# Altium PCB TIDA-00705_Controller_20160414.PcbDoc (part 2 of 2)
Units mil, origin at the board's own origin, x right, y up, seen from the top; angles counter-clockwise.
Board outline 1000 x 1000 mil, 4 copper layers (Top Layer, L2-GND-PLANE, L3-GND-PLANE, Bottom Layer), stack 0 mil thick; 95 components, 61 nets, 268 pads, 111 vias.
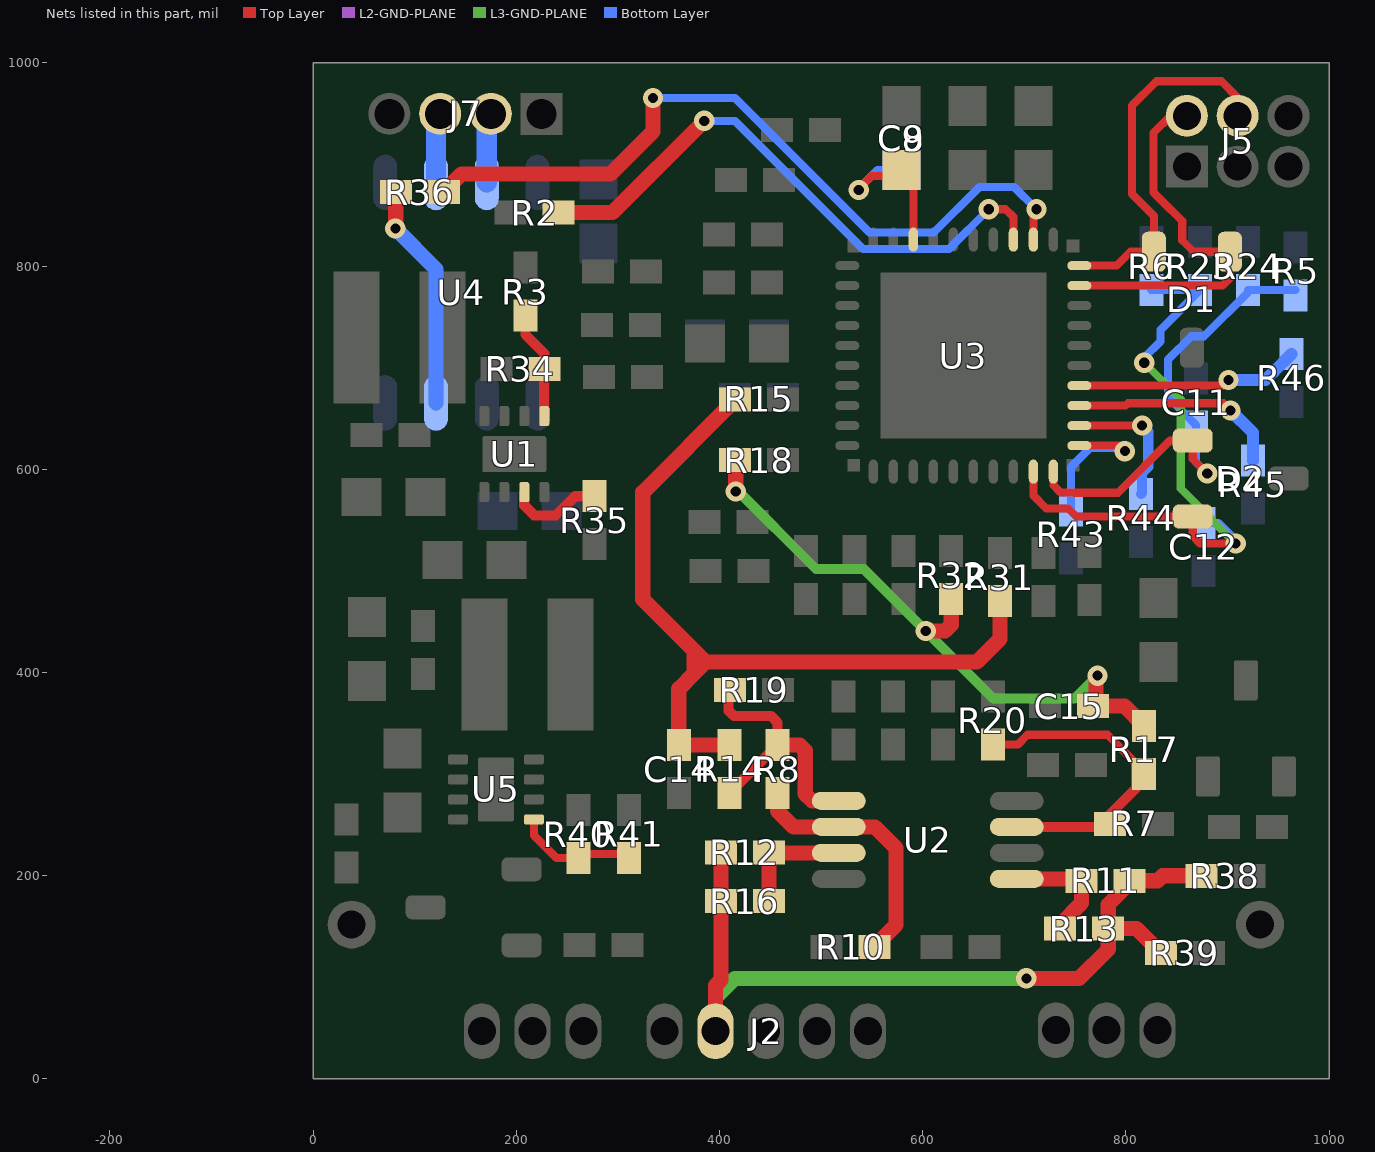
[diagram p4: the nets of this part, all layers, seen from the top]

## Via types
v1: diameter 20, hole 10, Top Layer to Bottom Layer, tented both sides, 76 vias
v2: diameter 20, hole 10, Top Layer to Bottom Layer, 26 vias
v3: diameter 19.68, hole 7.87, Top Layer to Bottom Layer, tented both sides, 5 vias
v4: diameter 19.68, hole 7.87, Top Layer to Bottom Layer, 4 vias

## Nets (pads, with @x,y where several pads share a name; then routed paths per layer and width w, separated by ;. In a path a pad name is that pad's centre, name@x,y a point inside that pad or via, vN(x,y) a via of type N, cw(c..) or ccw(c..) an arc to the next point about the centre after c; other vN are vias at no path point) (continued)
NetR7_2: R7.2 R17.1 R20.2 U2.7 | length 308.2
  Top Layer w8: R20.2@675,329.38 693.81,329.38 703.22,338.78 781.78,338.78 R17.1@810,310.57
  Top Layer w10: U2.7@692.6,248.13 772.13,248.13 810,286 R17.1@810,310.57
NetR8_1: R8.1 R10.2 U2.2 | length 255.6
  Top Layer w15: R8.1@457,281.38 457,263.96 473,247.96 552.87,248.13 573.62,227.38 573.62,151.62 R10.2@552,130
NetR8_2: R8.2 R14.1 R19.2 U2.1 | length 268.4
  Top Layer w10: R14.1@410,281.38 410,281.62 R8.2@457,328.62 457,351 450.63,357.37 414.13,357.37 409,362.5 409,373.62 R19.2@416.38,381
  Top Layer w15: R8.2@460,328.62 478.88,328.62 484.31,323.19 484.31,280.69 491.28,273.72 U2.1@517.4,273.72
NetR11_2: R11.2 R13.2 U2.5 | length 119.5
  Top Layer w15: U2.5@692.6,196.94 756.32,196.94 756.38,197 756.38,173.24 735.38,152.24 R13.2@735.38,150
NetR12_2: R12.2 R16.2 U2.3 | length 117.8
  Top Layer w15: R16.2@448.62,175 R12.2@448.62,223 ; R12.2@448.62,225 451.09,222.54 U2.3@517.4,222.54
NetR35_1: R35.1 U1.3 | length 94.1
  Top Layer w10: U1.3@207.84,577.6 207.84,564.59 217.68,554.76 239.13,554.76 258,573.62 R35.1@277,573.62
NetR36_1: R36.1 U4.3 | length 225.2
  Top Layer w15: v2(81,837) 81.38,837.38 R36.1@81.38,873
  L2-GND-PLANE w15: v2(81,837) v2@81,838
  Bottom Layer w15: v2(81,837) 121,797 U4.3@121,665.5
NetR43_1: R43.1 U3.11 | length 152.7
  Top Layer w8: U3.11@754.17,623.42 795.58,623.42 799,620 v1(799,618)
  Bottom Layer w8: R43.1@746,559.77 746,602.25 764.75,621 796,621 v1(799,618)
NetR44_1: R44.1 U3.12 | length 136.6
  Top Layer w8: U3.12@754.17,643.1 v1(816,643.1) v1@817.9,643.1
  Bottom Layer w10: R44.1@815,575.62 816,576.62 816,596.47 822,602.47 822,637.1 v1(816,643.1)
NetR45_1: R45.1 U3.13 | length 211.2
  Top Layer w8: U3.13@754.17,662.79 799.69,662.79 802,665.1 895.9,665.1 v1(903,658)
  Bottom Layer w12: v1(903,658) 925,636 R45.1@925,608.62
NetR46_1: R46.1 U3.14 | length 221.7
  Top Layer w8: U3.14@754.17,682.47 895.47,682.47 v1(901,688)
  Bottom Layer w12: v1(901,688) 937.26,688 945.39,696.13 945.5,696.13 R46.1@963,713.62
PHASE1_CBC: C14.1 R14.2 R15.1 R31.2 | length 824.9
  Top Layer w15: R14.2@410,328.62 C14.1@360,328.62 360,384 375,399 ; R15.1@415.38,668.32 324.5,577.44 324.5,472.12 375,421.62 ; R31.2@676,472.38 676,433 653.31,410.31 386.31,410.31 ; 375,399 375,421.62 ; 375,399 386.31,410.31 ; 375,421.62 386.31,410.31
PHASE2_CBC: C15.1 R17.2 R18.1 R32.2 | length 620.5
  Top Layer w15: R18.1@415.38,611 416,610.38 v1@416,581 ; v1(603,441) 622,441 628,447 R32.2@628,472.38 ; v1(772,397) 771.24,397 770.62,396.38 770.62,367 798.62,367 R17.2@818,347.62
  L3-GND-PLANE w10: v1@416,581 495,502 542,502 v1(603,441) 669.62,374.38 749.38,374.38 v1(772,397)
  other v1: 416,578.19
PMBUS-ALERT: D1.1 J5.2 U3.19 | length 386.1
  Top Layer w8: U3.19@754.28,781 U3.19@754.17,780.9 781.79,780.9 781.89,781 895,781 902.4,788.4 D1.1@902.4,814.24 866.76,814.24 855.5,825.5 855.5,844.5 834.67,865.33 834.36,865.33 827.33,872.36 827.33,931.33 844,948 J5.2@860,948
PMBUS-CLK: C12.1 D2.2 R6.1 R23.1 U3.9 | length 653.1
  Top Layer w8: U3.9@708.9,597.83 708.9,574.1 721.63,561.37 742.41,561.37 742.78,561 743.78,561 751.18,553.6 D2.2@865.76,553.6 865.76,534.24 873,527 v2(908,527)
  L3-GND-PLANE w8: v2(818.04,704.98) 854,669.02 854,581 v2(908,527)
  Bottom Layer w8: v2(818.04,704.98) 818.04,709.93 834,725.89 834,737.38 R23.1@873,776.38 R6.1@825,776.38 ; C12.1@876.38,547.24 891.19,547.24 908,530.43 v2(908,527)
PMBUS-CTRL: D1.2 J5.4 U3.20 | length 370.4
  Top Layer w8: U3.20@754.17,800.58 791,800.58 804.66,814.24 D1.2@827.6,814.24 827.6,849.33 806,870.93 806,958 830,982 894,982 910,966 J5.4@910,948
PMBUS-DATA: C11.1 D2.1 R5.1 R24.1 U3.10 | length 496.4
  Top Layer w8: U3.10@728.58,597.83 728.58,584.42 735.63,577.37 749.04,577.37 749.41,577 792.11,577 843.51,628.4 D2.1@865.76,628.4 865.76,610.24 v1(880,596)
  Bottom Layer w8: v1(880,596) 869,607 C11.1@869,642.38 869,643.84 841.49,671.35 841.49,708.02 864.47,731 877,731 920,774 R24.1@920,776.38 R5.1@967,776.38
SCI_RX: R2.2 U3.23 | length 578.6
  Top Layer w8: v1(665,856) 681.46,856 689.21,848.24 U3.23@689.21,826.17
  Top Layer w15: R2.2@241.62,852.75 294.75,852.75 v1(385,943)
  Bottom Layer w8: v1(385,943) 415.11,943 541.11,817 626,817 v1(665,856)
SCI_RX_ISO: J7.2 U4.7 | length 69.2
  Bottom Layer w20: U4.7@171,882.5 171,946 J7.2@175,950
SCI_TX: R36.2 U3.22 | length 754.8
  Top Layer w8: U3.22@708.9,826.17 708.9,852.9 v1(712,856)
  Top Layer w15: R36.2@128.62,873 146.24,890.62 292.62,890.62 334.5,932.5 v1(334.5,965.5)
  Bottom Layer w8: v1(334.5,965.5) 415.24,965.5 547.74,833 610.89,833 655.89,878 690,878 v1(712,856)
SCI_TX_ISO: J7.3 U4.6 | length 69.2
  Bottom Layer w20: U4.6@121,882.5 121,946 J7.3@125,950
V8.2FB: R40.1 R41.2 U5.5 | length 120.3
  Top Layer w8: U5.5@217.4,255.47 217.4,239.72 239.75,217.38 R40.1@261,217.38 ; R40.1@261,221.38 307,221.38 R41.2@311,217.38
VFB: R3.2 R34.1 U1.5 | length 106.7
  Top Layer w10: R3.2@209,751.38 209,732.63 227.62,714.01 R34.1@227.62,699 227.53,698.91 U1.5@227.53,652.4
VREF: C8.2 C9.1 U3.28 | length 174.5
  Top Layer w8: v1(537,875) 537,876 550,889 573.5,889 C8.2@579,894.5 590.79,882.72 U3.28@590.79,826.17
  Bottom Layer w8: v1(537,875) 537,876 555.5,894.5 C9.1@579,894.5
VREF_OA: J2.4 R11.1 R12.1 R13.1 R16.1 R38.1 R39.2 | length 828.2
  Top Layer w15: J2.4@396,47 396,92 401.38,97.38 R16.1@401.38,175 R12.1@401.38,223 ; v1(702,99) 754,99 782.62,127.62 R13.1@782.62,148 ; R39.2@834.38,124 810.38,148 R13.1@782.62,148 ; R38.1@874.38,200 836,200 831,195 R11.1@803.62,195 803.62,192.76 782.62,171.76 R13.1@782.62,148
  L3-GND-PLANE w15: J2.4@396,47 396,80 415,99 v1(702,99)
pads on no net: D4.3 U1.4 U1.8 U3.2 U3.8 U3.15 U3.21 U3.24 U3.25 U3.42 U5.4 U5.8

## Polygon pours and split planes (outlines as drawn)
GND on Bottom Layer "Top Layer-No Net" (solid, remove dead copper, pour order 14): 37.2,987.2 10,960 10,611 10,37 10,22 22,10 977,10 978,10 990,22 990,978 978,990
BUS+ on Top Layer "Top Layer-No Net" (solid, remove dead copper, pour order 21): 180,586 180,579 180,557 169,546 168,545 168,533 168,492 170,490 171,489 180,489 283,489 287,493 290,496 290,510 290,542 288,544 280,544 205,544 198,551 197,552 197,564 197,587 194,590 187,590 182.46,590 180,587.54
NetL1_1 on Top Layer "Top Layer-No Net" (solid, remove dead copper, pour order 19): 100,801 100,764 100,663 105,658 109,654 150,654 163,667 177,667 178,667 180,665 180,660 180,642 181,641 186,641 193,641 194,642 195,643 195,647 195,679 193,681 192,682 176,682 163,682 158,687 158,700 158,799 153,804 121,804 103,804
3.3V on Top Layer "Top Layer-No Net" (solid, remove dead copper, pour order 17): 16,785 16,735 16,530 27,519 34,512 57,512 72,512 75,515 77,517 77,603 77,806 68,815 67,816 49.54,816 28,816 16,804
GND on Top Layer "Top Layer-No Net" (solid, remove dead copper, pour order 13): 37.2,987.2 10,960 10,611 10,37 10,22 22,10 977,10 978,10 990,22 990,978 978,990
BUS+ on Top Layer "Top Layer-No Net" (solid, remove dead copper, pour order 8): 30.54,293.04 17.5,280 17.5,257 17.5,242.5 22,238 23,237 37,237 106.98,237 111,241.02 113,243.02 113,255 113,274 115,276 124,285 140,285 151,285 153,287 154,288 154,294 154,302 152,304 138,304 41.5,304
8.2V on Top Layer "Top Layer-No Net" (solid, remove dead copper, pour order 10): 20,496 20,450 20,444 25,439 29,435 64,435 86,435 91,430 94,427 112,427 131,427 134,424 139,419 139,369 139,346 144,341 152,341 192,341 198,347 198,359 198,470 194,474 192,476 123,476 93.18,476 80.2,488.98 65.18,504 28,504
NetL2_1 on Top Layer "Top Layer-No Net" (solid, remove dead copper, pour order 12): 209,302 227,302 229,304 235,310 235,322 229,328 229,346 229,472 233,476 265,476 283,476 287,472 290,469 290,447 290,302.5 280.5,293 261,293 239,293 233,287 213,287 209,287 205,291 205,297 205,299 208,302
GND on L3-GND-PLANE "Top Layer-No Net" (solid, remove dead copper, pour order 11): 36.2,987.2 9,960 9,611 9,37 9,22 21,10 976,10 977,10 989,22 989,978 977,990
GND on L2-GND-PLANE "Top Layer-No Net" (solid, remove dead copper, pour order 9): 37.2,987.2 10,960 10,611 10,37 10,22 22,10 977,10 978,10 990,22 990,978 978,990

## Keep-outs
Keep-Out Layer:
  lines w6: 10,10 990,10 990,990 10,990 10,10
  text ".Layer_Name" at 577,-858.49 h60

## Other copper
Top Layer:
  pour cut-out: 16,913 12,909 10,909 10,913 12.16,915.16
  pour cut-out: 10,917.33 14.33,913 218,913 290,913 308,931 308,981 299,990 24,990 10,976
  text ".Layer_Name" at 577,-858.49 h60
L2-GND-PLANE:
  pour cut-out: 10,917.33 14.33,913 218,913 290,913 308,931 308,981 299,990 24,990 10,976
  pour cut-out: 16,913 12,909 10,909 10,913 12.16,915.16
  text ".Layer_Name" at 612,-866 h60
L3-GND-PLANE:
  pour cut-out: 16,913 12,909 10,909 10,913 12.16,915.16
  pour cut-out: 10,917.33 14.33,913 218,913 290,913 308,931 308,981 299,990 24,990 10,976
  text ".Layer_Name" at 640,-860 h60
Bottom Layer:
  pour cut-out: 10,917.33 14.33,913 218,913 290,913 308,931 308,981 299,990 24,990 10,976
  pour cut-out: 16,913 12,909 10,909 10,913 12.16,915.16
  text ".Layer_Name" at 577,-858.49 h60

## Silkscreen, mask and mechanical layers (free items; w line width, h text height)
Top Overlay:
  circle w10: c717.72,111 r7.28
  circle w10: c109,82 r7.28
  lines w6: 45,668 45,677 ; 313,656 350,656 375,681 ; 315,881 323,873 352,873 373.5,851.5 375,851.5 ; 347,832 350,832 363,819 363,804 363,782 368,777 372,777 ; 477,558 788,558 799,547 799,514 ; 539,854 604.78,854 616.8,866.02 ; 550,436 787,436 795,444 ; 664,180 684,160 702,160 ; 681,58 681,97 ; 718,184 725,184 ; 801,536 810,536 ; 10,581 20,571 147.01,571 176.01,542 243,542 260,559 260,605 246,619 223,642 191.98,642 166.98,667 19,667 10,658 10,581
  text "A" at 51,679 h30 r90
  text "A" at 810,527 h30
  text ".Layer_Name" at 577,-858.49 h60
Bottom Overlay:
  lines w6: 844,587.99 844,596.5 854,606.5
  text "TIDA-00705" at 334,431 h35
  text "Rev E1" at 278,381 h40
  text ".Layer_Name" at 577,-858.49 h60
Top Paste:
  text ".Layer_Name" at 577,-858.49 h60
Bottom Paste:
  text ".Layer_Name" at 577,-858.49 h60
Top Solder:
  text ".Layer_Name" at 577,-858.49 h60
  text ".Layer_Name" at 577,-858.49 h60
Bottom Solder:
  text ".Layer_Name" at 577,-858.49 h60
Drill Guide:
  text ".Layer_Name" at 577,-858.49 h60
M1 Board Outline:
  lines w5.98: 0,0 0,1000 1000,1000
  lines w6: 0,0 0,1000 1000,1000 ; 0,0 1000,0 ; 0,0 1000,0 ; 1000,0 1000,1000 ; 1000,0 1000,1000
  text ".Layer_Name" at 567,-866 h60
M2 Board Dimensions:
  rectangle: -0.5,-285.5 124.5,-160.5
  rectangle: 124.5,-410.5 499.5,-285.5
  lines w7: -0.5,-285.5 999.5,-285.5 ; 124.5,-410.5 124.5,-160.5 ; 249.5,-410.5 249.5,-160.5 ; 499.5,-410.5 499.5,-160.5 ; 749.5,-410.5 749.5,-160.5 ; -0.5,-410.5 999.5,-410.5 999.5,-160.5 -0.5,-160.5 -0.5,-410.5
  lines w10: -0.5,-475.5 -0.5,-455.5 ; 59.5,-485.5 -0.5,-465.5 ; 59.5,-445.5 -0.5,-465.5 ; 223.58,-465.5 -0.5,-465.5 ; 775.42,-465.5 999.5,-465.5 ; 939.5,-485.5 999.5,-465.5 ; 939.5,-445.5 999.5,-465.5 ; 999.5,-475.5 999.5,-455.5
  text "1000 (mil)" at 233.58,-501.49 h60
M3 3D STEP Top:
  text ".Layer_Name" at 577,-858.49 h60
M4 3D STEP Bottom:
  text ".Layer_Name" at 577,-858.49 h60
M5 Assembly Top:
  circle w15: c551,624 r6
  circle w10: c166,47 r9.22
  circle w10: c555,47 r9.22
  circle w10: c740,48 r9.22
  circle w10: c226,929 r9.22
  circle w10: c933,812 r9.22
  circle w10: c865,654 r9.22
  circle w6: c856,302 r9.22
  lines w10: -292,-930.17 6308,-930.17 ; -292,-726.83 6310,-726.83 ; -292,-523.5 -292,-1133.5 3713,-1133.5 6310,-1133.5 6310,-523.5 -291.5,-523.5 -291.5,-1133.5 1284,-1133.5 ; 2173,-1133.5 2173,-523.5 ; 3735,-726 3735,-522.67 ; 4280,-726.83 4280,-523.5 ; 4902,-1140 4902,-937.17
  text "COMPONENTS MARKED 'DNP' SHOULD NOT BE POPULATED." at 1153.5,-318.5 h30
  text "ASSEMBLY VARIANT:" at 1153,-434 h30
  text ".VariantName" at 2189,-434 h30
  text "PCB VIEWED FROM TOP SIDE" at -228.5,-655.67 h30
  text "BOARD #:" at 2248,-655.67 h30
  text "ISE-PLC-AIM-300" at 2793.5,-655.67 h30
  text "SVN REV:" at 4476,-655.67 h30
  text ".VersionControl_RevNumber" at 4982,-655.67 h30
  text "REV: E1" at 3805,-660 h30
  text "IGNORE ->" at -228.5,-858.49 h30
  text ".LAYER_Name" at 586,-863 h60
  text "PLOT NAME =" at -228.5,-1064.34 h30
  text ".plot_File_Name" at 577,-1064.34 h30
  text "GENERATED    :" at 2250,-1064.34 h30
  text ".Print_Date" at 3119.5,-1064.34 h30
  text ".Print_Time" at 3848.5,-1064.34 h30
  text "TEXAS INSTRUMENTS" at 5113,-1064.34 h30
M6 Assembly Bottom:
  lines w10: -292.5,-727.33 6309.5,-727.33 ; -290.5,-930.67 6309.5,-930.67 ; 1115.5,-1140.5 1115.5,-937.67 ; 1737.5,-727.33 1737.5,-524 ; 2236,-723 2236,-519.67 ; 3844.5,-1134 3844.5,-524 ; 4733.5,-1134 6309,-1134 6309,-524 -292.5,-524 -292.5,-1134 2304.5,-1134 6309.5,-1134 6309.5,-524
  text "COMPONENTS MARKED 'DNP' SHOULD NOT BE POPULATED." at 6102,-318 h60
  text ".VariantName" at 5058,-434 h60
  text "ASSEMBLY VARIANT:" at 6097,-434 h60
  text "REV: E1" at 2173,-655 h60
  text ".VersionControl_RevNumber" at 1035.5,-656.17 h60
  text "SVN REV:" at 1541.5,-656.17 h60
  text "ISE-PLC-AIM-300" at 3224,-656.17 h60
  text "BOARD #:" at 3769.5,-656.17 h60
  text "PCB VIEWED FROM BOTTOM SIDE" at 6246,-656.17 h60
  text ".layer_Name" at 5851,-844 h60
  text "IGNORE ->" at 2547.85,-858.49 h60
  text "TEXAS INSTRUMENTS" at 904.5,-1064.84 h60
  text ".Print_Time" at 2169,-1064.84 h60
  text ".Print_Date" at 2898,-1064.84 h60
  text "GENERATED    :" at 3767.5,-1064.84 h60
  text ".plot_File_Name" at 5440.5,-1064.84 h60
  text "PLOT NAME =" at 6246,-1064.84 h60
M7 LPKF Text Top:
  lines w6: 16.94,472 16.94,180.66 17.61,180 954.46,180 956,181.54 956,470.76 954.82,471.95 17,471.95 18.06,470.88
M9 Title Sheet:
  drawing of 56 lines, arcs and shapes, not listed
  text "1" at 320.58,8044.9 h70
  text "2" at 3262.11,8044.9 h70
  text "3" at 5702.71,8044.9 h70
  text "4" at 8212.65,8044.9 h70
  text "5" at 10776.84,8044.9 h70
  text "6" at 13282.14,8044.9 h70
  text "A" at -399.13,6895.37 h70
  text "A" at 14398.02,6895.37 h70
  text "B" at -399.13,4636.49 h70
  text "B" at 14398.02,4636.49 h70
  text "C" at -399.13,2204.83 h70
  text "C" at 14398.02,2204.83 h70
  text "PROJECT TITLE:" at 11348.77,257.82 h45
  text ".PRJ_Title" at 11440.27,127.32 h70
  text "DESIGNED FOR:" at 11335.61,-31.74 h45
  text ".PRJ_Customer" at 11385.61,-171.74 h70
  text "D" at -399.13,-301.67 h70
  text "D" at 14398.02,-301.67 h70
  text "FILE NAME:" at 11347.5,-340.46 h45
  text ".PCB_File_Name_No_Path" at 11397.5,-460.46 h70
  text "ENGINEER:" at 11346.95,-611.59 h45
  text "LAYOUT BY:" at 12838.93,-618.58 h45
  text "Texas Instruments (TI) and/or its licensors do not warrant the accuracy or completeness of this specification" at 6354,-620.34 h45
  text "or any information contained therein. TI and/or its licensors do not warrant that this design will meet" at 6309.01,-733 h45
  text ".PRJ_Engineer" at 11396.95,-766.58 h70
  text ".pcb_Layout" at 12889.43,-773.57 h70
  text "the specifications, will be suitable for your application or fit for any particular purpose, or will operate in" at 6309.01,-845.67 h45
  text "ALTIUM DESIGNER VERSION:" at 12898.63,-941.77 h45
  text "an implementation. TI and/or its licensors do not warrant that the design is production worthy. You should" at 6309.01,-958.34 h45
  text ".print_Scale" at 11409.34,-1034.04 h70
  text "completely validate and test your design implementation to confirm the system functionality for your application." at 6354,-1071 h45
  text ".Application_BuildNumber" at 12949.13,-1075.1 h70
  text "2" at 3053.82,-1263.03 h70
  text "6" at 13023.96,-1272.7 h70
  text "3" at 5383.82,-1277.08 h70
  text "5" at 10535.37,-1280.63 h70
  text "4" at 7991.08,-1283.6 h70
  text "1" at 443.36,-1291.02 h70
M10 Fab Notes:
  drawing of 220 lines, arcs and shapes, not listed
  text "DESIGN INFORMATION" at 12381.02,6810 h60
  text "(REFER ALSO ARRAY/PANEL PROFILING INFORMATION)" at 12019.46,6648.29 h60
  text "BOARD SIZE" at 11333.46,6644 h60
  text "1000MIL" at 11795.78,6516.18 h60
  text "X" at 12301.46,6516.18 h60
  text "1000MIL" at 12532.78,6516.18 h60
  text "Number of Layers :" at 11736.46,6319 h60
  text "4" at 12831.27,6309 h60
  text "MIN. TRACK WIDTH:" at 11736.46,6180 h60
  text "8" at 12832.7,6180 h60
  text "MIL" at 12987.46,6180 h60
  text "MIN. CLEARANCE:" at 11736.46,6048 h60
  text "MIL" at 12987.46,6048 h60
  text "7.769" at 12686,6047 h60
  text "MIN. VIA PAD SIZE:" at 11736.46,5916 h60
  text "20" at 12802.71,5916 h60
  text "MIL" at 12987.46,5916 h60
  text "0.036mm (1.435MIL)" at 12431.46,5774.29 h60
  text "EXTERNAL" at 13310,5773 h60
  text "MINIMUM ANNULAR RING" at 11407.23,5770 h60
  text "PER" at 11607.23,5652 h60
  text "IPC-D-275 CLASS 2 LEVEL C" at 11827.23,5652 h60
  text "MIL, HOLES" at 13315.46,5539.71 h60
  text "+/-" at 12923,5539 h60
  text "+/-" at 13777,5539 h60
  text "REGISTRATION TOLERANCES:" at 11407.23,5534 h60
  text "METAL" at 12607,5534 h60
  text "5" at 13183.2,5534 h60
  text "3" at 14016.2,5534 h60
  text "MIL" at 14132.46,5534 h60
  text "MATERIAL:" at 11332.46,5324.54 h60
  text "FR-4 High Tg" at 12318.9,5184.21 h60
  text "FR-408" at 11753.46,5175.64 h60
  text "OTHER" at 13241.46,5175.64 h60
  text "X" at 12153,5175 h60
  text "63 MIL (1.6mm) +/-10%" at 12073.56,5012.92 h60
  text "THICKNESS:" at 11407.23,5008.64 h60
  text "X" at 11945.4,5008.64 h60
  text "OTHER" at 13358.46,5008.64 h60
  text "TOLERANCE:" at 11407.23,4850.64 h60
  text "X" at 12246.53,4850.64 h60
  text "ANSI IPC-6012 TYPE 3 CLASS 2" at 12433.48,4850.64 h60
  text "OTHER +/-" at 12433.46,4694.64 h60
  text "BOW & TWIST:" at 11407.23,4537.64 h60
  text "X" at 12246.53,4537.64 h60
  text "ANSI IPC-6012 TYPE 3 CLASS 2" at 12433.48,4537.64 h60
  text "OTHER +/-" at 12433.46,4379.13 h60
  text "COPPER THICKNESS (FINISHED):" at 11332.46,4243.64 h60
  text "1.4MIL (1oz)" at 12212.46,4090.92 h60
  text "2MIL (1.4oz)" at 12979.46,4090.92 h60
  text "2.8MIL (2oz)" at 13706.46,4090.92 h60
  text "OUTER:" at 11689.46,4086.64 h60
  text "X" at 13582,4087 h60
  text "1.4MIL (1oz)" at 12212.46,3933.92 h60
  text "2.8MIL (2oz)" at 12979.46,3933.92 h60
  text "N/A" at 13706,3934.29 h60
  text "INNER SIGNAL:" at 11400.38,3929.64 h60
  text "X" at 12085.42,3929.64 h60
  text "DRILLING:" at 11332.46,3790.64 h60
  text "REFERENCE:" at 11407.23,3673.64 h60
  text "X" at 12055.46,3673.64 h60
  text "AS SHOWN" at 12242.46,3673.64 h60
  text "X" at 12956.46,3673.64 h60
  text "NC_DRILL FILES" at 13093.46,3673.64 h60
  text "PTH MIN COPPER THICKNESS:" at 11407.23,3515.64 h60
  text "X" at 12757.46,3515.64 h60
  text "1MIL" at 12894.46,3515.64 h60
  text "OTHER" at 13391.46,3515.64 h60
  text "BOARD FINISH:" at 11332.46,3356.64 h60
  text "SILKSCREEN:" at 11487.68,3238.64 h60
  text "X" at 12436.46,3238.64 h60
  text "TOP" at 12562.46,3238.64 h60
  text "X" at 12946.46,3238.64 h60
  text "BOTTOM" at 13073.46,3238.64 h60
  text "SILKSCREEN COLOR:" at 11486.01,3072.64 h60
  text "X" at 12433.75,3072.64 h60
  text "WHITE" at 12560.79,3072.64 h60
  text "OTHER" at 13071.79,3072.64 h60
  text "SOLDER RESIST COLOR:" at 11592.01,2921.64 h60
  text "GREEN" at 12286.79,2762.44 h60
  text "X" at 12049,2750 h60
  text "BLUE" at 12857,2744 h60
  text "OTHER" at 13306,2740 h60
  text "IMMERSION GOLD (ENIG)" at 12393.46,2553.92 h60
  text "ENEPIG" at 13731,2550.64 h60
  text "SURFACE FINISH:" at 11332.46,2549.64 h60
  text "X" at 12206.51,2549.64 h60
  text "IMM. TIN/SILVER OR EQUIV" at 11662,2392.64 h60
  text "OTHER" at 13093.46,2392.64 h60
  text "ARRAY/PANEL:" at 11332.46,2213.64 h60
  text "CUT AND TRIM PER MECH LAYER 1" at 12393.46,2209.35 h60
  text "N.C. ROUTE" at 12393.46,2057.64 h60
  text "X" at 13072.46,2057.64 h60
  text "V. SCORE" at 13259.46,2057.64 h60
  text "CERTIFICATION:" at 11332.46,1920.64 h60
  text "MATERIALS AND WORKMANSHIP FOR ALL PCBS" at 12057.46,1920.64 h60
  text "TO MEET OR EXCEED THE REQUIREMENTS OF:" at 12057.46,1822.64 h60
  text "X" at 11683.96,1686.13 h60
  text "ANSI IPC-A-600F CLASS ->" at 11822.96,1686.13 h60
  text "X" at 13462.02,1686.13 h60
  text "2" at 13580.96,1686.14 h60
  text "1" at 13265.96,1684.64 h60
  text "3" at 13934.96,1684.64 h60
  text "X" at 11686.02,1526.64 h60
  text "UL 94V-0" at 11822.96,1526.64 h60
  text "X" at 12498.02,1526.64 h60
  text "RoHS" at 12634.96,1526.64 h60
  text "OTHER" at 13279.36,1526.64 h60
  text "PER ORDER" at 13676.42,1526.64 h60
  text "ADDITIONAL REQUIREMENTS:" at 11332.46,1385.64 h60
  text "VIA TENTING:" at 12807,1292.36 h60
  text "X" at 13595.29,1292.48 h60
  text "YES" at 13378.67,1283.28 h60
  text "NO" at 13773.47,1283.05 h60
  text "MICROSECTION:" at 11407.23,1270.64 h60
  text "YES" at 12312.96,1270.64 h60
  text "REQUIRED" at 13174.46,1114.49 h60
  text "BARE BOARD ELEC. TEST:" at 11407.23,1111.64 h60
  text "NONE" at 12712.96,1111.64 h60
  text "X" at 13047.46,1111.64 h60
  text "PER ORDER" at 13766.46,1111.64 h60
  text "MANUFACTURER'S UL:" at 11407.23,954.64 h60
  text "RAIL" at 12572.96,950.35 h60
  text "METAL" at 13064.77,950.35 h60
  text "X" at 13440,950 h60
  text "SILK" at 13576.46,950.35 h60
M11 Gerber Information:
  lines w10: -292,-930.17 6308,-930.17 ; -292,-726.83 6310,-726.83 ; -292,-523.5 -292,-1133.5 3713,-1133.5 6310,-1133.5 6310,-523.5 -291.5,-523.5 -291.5,-1133.5 1284,-1133.5 ; 2173,-1133.5 2173,-523.5 ; 3690,-730 3690,-526.67 ; 4280,-726.83 4280,-523.5 ; 4902,-1140 4902,-937.17
  text "ALL ARTWORK VIEWED FROM TOP SIDE" at -228.5,-655.67 h60
  text "BOARD #:" at 2248,-655.67 h60
  text "SVN REV:" at 4476,-655.67 h60
  text ".VersionControl_RevNumber" at 4982,-655.67 h60
  text "REV: E1" at 3785,-657 h60
  text "ISE-PLC-AIM-300" at 2720,-660 h60
  text "LAYER NAME =" at -228.5,-858.49 h60
  text "PLOT NAME =" at -228.5,-1064.34 h60
  text ".plot_File_Name" at 577,-1064.34 h60
  text "GENERATED    :" at 2250,-1064.34 h60
  text ".Print_Date" at 3119.5,-1064.34 h60
  text ".Print_Time" at 3848.5,-1064.34 h60
  text "TEXAS INSTRUMENTS" at 5113,-1064.34 h60
M12 Stackup:
  drawing of 295 lines, arcs and shapes, not listed
  text "Layer" at 6394,7460 h60
  text "Name" at 6803.91,7460 h60
  text "Material" at 7733.66,7460 h60
  text "Thickness" at 8593.42,7460 h60
  text "Constant" at 9243.26,7460 h60
  text "Board Layer Stack" at 9813.12,7460 h60
  text "1" at 6394,7340 h60
  text "Top Overlay" at 6803.91,7340 h60
  text "2" at 6394,7220 h60
  text "Top Solder" at 6803.91,7220 h60
  text "Solder Resist" at 7733.66,7220 h60
  text "0" at 9243.26,7220 h60
  text "3" at 6394,7100 h60
  text "Top Layer" at 6803.91,7100 h60
  text "Copper" at 7733.66,7100 h60
  text "4" at 6394,6980 h60
  text "Dielectric1" at 6803.91,6980 h60
  text "FR-4 High Tg" at 7733.66,6980 h60
  text "0" at 9243.26,6980 h60
  text "5" at 6394,6860 h60
  text "L2-GND-PLANE" at 6803.91,6860 h60
  text "Copper" at 7733.66,6860 h60
  text "6" at 6394,6740 h60
  text "Dielectric2" at 6803.91,6740 h60
  text "FR-4 High Tg" at 7733.66,6740 h60
  text "0" at 9243.26,6740 h60
  text "7" at 6394,6620 h60
  text "L3-GND-PLANE" at 6803.91,6620 h60
  text "Copper" at 7733.66,6620 h60
  text "8" at 6394,6500 h60
  text "Dielectric3" at 6803.91,6500 h60
  text "FR-4 High Tg" at 7733.66,6500 h60
  text "0" at 9243.26,6500 h60
  text "9" at 6394,6380 h60
  text "Bottom Layer" at 6803.91,6380 h60
  text "Copper" at 7733.66,6380 h60
  text "10" at 6394,6260 h60
  text "Bottom Solder" at 6803.91,6260 h60
  text "Solder Resist" at 7733.66,6260 h60
  text "0" at 9243.26,6260 h60
  text "11" at 6394,6140 h60
  text "Bottom Overlay" at 6803.91,6140 h60
M13 Component Bodies Top:
  text ".Layer_Name" at 577,-858.49 h60
M14 Component Bodies Bottom:
  text ".Layer_Name" at 577,-858.49 h60
M15 Courtyards Top:
  text ".Layer_Name" at 577,-858.49 h60
M16 Courtyards Bottom:
  text ".Layer_Name" at 577,-858.49 h60
Drill Drawing:
  circle w1: c1914.12,1255 r25
  lines w1: 1889.12,1130 1939.12,1130 1914.12,1080 1889.12,1130 ; 1889.12,1380 1939.12,1380 1939.12,1430 1889.12,1430 1889.12,1380 ; 1889.12,1542.5 1901.62,1542.5 1914.12,1530 1926.62,1542.5 1939.12,1542.5 1926.62,1555 1939.12,1567.5 1926.62,1567.5 1914.12,1580 1901.62,1567.5 1889.12,1567.5 1901.62,1555 1889.12,1542.5
  lines w15: 1821,1035 5699.97,1035 ; 1821,1635 5699.97,1635 ; 2371.88,885 2371.88,1785 ; 3069.69,885 3069.69,1785 ; 4415.29,885 4415.29,1785 ; 4921.17,885 4921.17,1785 ; 1821,885 5699.97,885 5699.97,1785 1821,1785 1821,885
  text "Board thickness is 1.6mm with 4 layers with External 2(OZ) and Internal 1(OZ) copper." at 6292,5879 h60
  text "As per board thickness vendor can adjust dielectric thickness." at 6283,5775 h60
  text "This is not an Impedance control board." at 6272,5664 h60
  text "Symbol" at 1911,1680 h72
  text "Hit Count" at 2416.88,1680 h72
  text "Finished Hole Size" at 3114.69,1680 h72
  text "Plated" at 4460.29,1680 h72
  text "Hole Type" at 4966.17,1680 h72
  text "4" at 2416.88,1530 h60
  text "29.53mil (0.750mm)" at 3114.69,1530 h60
  text "PTH" at 4460.29,1530 h60
  text "Round" at 4966.17,1530 h60
  text "9" at 2416.88,1380 h60
  text "7.87mil (0.200mm)" at 3114.69,1380 h60
  text "PTH" at 4460.29,1380 h60
  text "Round" at 4966.17,1380 h60
  text "19" at 2416.88,1230 h60
  text "27.56mil (0.700mm)" at 3114.69,1230 h60
  text "PTH" at 4460.29,1230 h60
  text "Round" at 4966.17,1230 h60
  text "102" at 2416.88,1080 h60
  text "10.00mil (0.254mm)" at 3114.69,1080 h60
  text "PTH" at 4460.29,1080 h60
  text "Round" at 4966.17,1080 h60
  text "134 Total" at 2416.88,930 h60
  text "Drill Table" at 1793,714 h60
  text "FOR 10MIL DRILL +0/-10MIL" at 1853,579 h60
  text "FOR 7.87MIL DRILL +0/-7.87MIL" at 1846,487 h60
  text "FOR PTH +3/-3MIL" at 1844,394 h60
  text ".Layer_Name" at 577,-858.49 h60

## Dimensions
0,1000 to 1000,1000 on M2 Board Dimensions
1000,1000 to 1000,0 on M2 Board Dimensions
